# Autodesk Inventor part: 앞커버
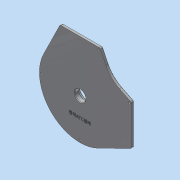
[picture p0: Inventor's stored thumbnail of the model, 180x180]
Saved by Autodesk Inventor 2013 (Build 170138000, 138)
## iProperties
Created: 2017-05
Part Number: 앞커버
Material: 알루미늄 6061
Document SubType Name: Modeling
Designer: mduedu
Density: 2.71 g/cm^3
Mass: 321.629 g
Surface Area: 500.043 cm^2
Volume: 118.682 cm^3
Author: mduedu
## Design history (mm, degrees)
sketch "스케치1"
  geometry: L1 (-71.801, 35.28)-(-40, 100); L2 (-40, 100)-(40, 100); L3 (40, 100)-(52.248, 75.073); L4 (35.28, 71.801)-(59.768, 59.768); L5 (100, 40)-(100, -40); L6 (100, -40)-(35.28, -71.801); L7 (75.073, 52.248)-(100, 40); L8 (59.768, 59.768)-(71.801, 35.28); L9 (33.075, -67.313)-(95, -36.886); L10 (95, -36.886)-(95, 36.886); L11 (95, 36.886)-(72.868, 47.76); L12 (47.76, 72.868)-(36.886, 95); L13 (36.886, 95)-(-36.886, 95); L14 (-36.886, 95)-(-67.313, 33.075); A1 r 80 centre (0, 0) between (71.801, 35.28) and (-71.801, 35.28); A2 r 80 centre (0, 0) between (35.28, -71.801) and (71.801, 35.28); A3 r 80 centre (0, 0) between (-71.801, 35.28) and (35.28, -71.801); A4 r 50 centre (97.123, 97.123) between (52.248, 75.073) and (75.073, 52.248); A5 r 55 centre (97.123, 97.123) between (47.76, 72.868) and (72.868, 47.76); A6 r 75 centre (0, 0) between (-67.313, 33.075) and (33.075, -67.313); 3 further points
  constraints: 29 end point, 15 tangent, 14 point on circle, 6 centre point, 2 midpoint, 2 perpendicular, 2 point on line, 1 coincident, 1 horizontal, 1 horizontal alignment, 1 vertical alignment, 6 other
  dimensions: "d0" = 160 diameter of A1; "d1" = 100 distance from line of L2 point (0, 0); "d2" = 100 distance from line of L5 point (0, 0); "d3" = 80 distance of L1.end L2.end; "d4" = 80 distance of L5.start L5.end; "d5" = 50 radius of A4; "d6" = 5 distance between parallel lines of L13 L2
extrude "돌출1" new body sketch "스케치1" distance "d7" = 5; taper "d8" = 0 deg
fillet "모깎기1" dims "d9" = 3
sketch "스케치2"
  geometry: C1 r 22 at (0, 0); 1 further point
  constraints: 1 centre point, 1 coincident
  dimensions: "d10" = 44 diameter of C1
extrude "돌출2" join sketch "스케치2" distance "d11" = 12.5; taper "d12" = 0 deg
sketch "스케치3"
  geometry: C1 r 18.5 at (0, 0); 1 further point
  constraints: 1 centre point, 1 coincident
  dimensions: "d13" = 37 diameter of C1
extrude "돌출3" cut sketch "스케치3" distance "d14" = 9; taper "d15" = 0 deg
hole "구멍1" diameter "d18" = 20; stored, may be unused: countersink angle "d22" = 90 deg, drill point angle "d24" = 118 deg; dims "d16" = 10, "d17" = 10, "d19" = 6, "d20" = 4, "d21" = 2, "d23" = 8
fillet "모깎기2" dims "d25" = 3
chamfer "모따기1" distance "d27" = 1; stored, may be unused: second distance "d28" = 2, angle "d29" = 45 deg
sketch "스케치4"
  geometry: 2 further points
  constraints: 1 vertical alignment, 1 other
  dimensions: "d30" = 35 distance of point (0, -35) point (0, 0)
feature "엠보싱1" sketch "스케치4" dims "d31" = 0.5, "d32" = 0
chamfer "모따기2" distance "d33" = 1; stored, may be unused: second distance "d34" = 2, angle "d35" = 45 deg
chamfer "모따기3" distance "d36" = 1; stored, may be unused: second distance "d37" = 2, angle "d38" = 45 deg
sketch "스케치5"
  geometry: L1 (18.989, -35.003)-(17.659, -35.003) reference; L2 (17.659, -35.003)-(17.659, -34.623) reference; L3 (17.659, -34.623)-(18.989, -34.623) reference; L4 (18.989, -34.623)-(18.989, -32.045) reference; L5 (18.989, -32.045)-(19.315, -32.045) reference; L6 (19.45, -32.31)-(19.45, -37.982) reference; L7 (19.45, -37.982)-(18.989, -37.982) reference; L8 (18.989, -37.982)-(18.989, -35.003) reference; L9 (-13.942, -34.352)-(-13.942, -34.746) reference; L10 (-13.942, -34.746)-(-15.061, -34.746) reference; L11 (-15.061, -34.746)-(-15.061, -36.489) reference; L12 (-15.061, -36.489)-(-15.536, -36.489) reference; L13 (-15.536, -36.489)-(-15.536, -31.998) reference; L14 (-15.536, -31.998)-(-15.231, -31.998) reference; L15 (-15.061, -32.263)-(-15.061, -34.352) reference; L16 (-15.061, -34.352)-(-13.942, -34.352) reference; L17 (-14.844, -37.439)-(-14.844, -37.819) reference; L18 (-14.844, -37.819)-(-19.193, -37.819) reference; L19 (-19.193, -37.819)-(-19.193, -36.191) reference; L20 (-19.193, -36.191)-(-18.84, -36.191) reference; L21 (-18.731, -36.408)-(-18.731, -37.439) reference; L22 (-18.731, -37.439)-(-14.844, -37.439) reference; L23 (-17.374, -32.575)-(-18.853, -32.575) reference; L24 (-18.853, -32.575)-(-18.853, -32.222) reference; L25 (-18.853, -32.222)-(-17.374, -32.222) reference; L26 (-17.374, -32.222)-(-17.374, -32.575) reference; L27 (-20.047, -33.382)-(-20.047, -33.029) reference; L28 (-20.047, -33.029)-(-16.282, -33.029) reference; L29 (-16.282, -33.029)-(-16.282, -33.382) reference; L30 (-16.282, -33.382)-(-20.047, -33.382) reference; L31 (-2.917, -37.615)-(-3.474, -36.089) reference; L32 (-3.474, -36.089)-(-5.726, -36.089) reference; L33 (-5.726, -36.089)-(-6.296, -37.615) reference; L34 (-6.296, -37.615)-(-6.777, -37.615) reference; L35 (-6.777, -37.615)-(-4.878, -32.615) reference; L36 (-4.878, -32.615)-(-4.335, -32.615) reference; L37 (-4.335, -32.615)-(-2.436, -37.615) reference; L38 (-2.436, -37.615)-(-2.917, -37.615) reference; L39 (-4.613, -33.104)-(-5.57, -35.675) reference; L40 (-5.57, -35.675)-(-3.636, -35.675) reference; L41 (-3.636, -35.675)-(-4.613, -33.104) reference; L42 (-10.095, -35.851)-(-8.284, -35.851) reference; L43 (-8.284, -35.851)-(-8.284, -37.975) reference; L44 (-8.284, -37.975)-(-8.745, -37.975) reference; L45 (-8.745, -37.975)-(-8.745, -36.225) reference; L46 (-8.745, -36.225)-(-12.578, -36.225) reference; L47 (-12.578, -36.225)-(-12.578, -35.851) reference; L48 (-12.578, -35.851)-(-10.55, -35.851) reference; L49 (-10.55, -35.851)-(-10.55, -34.63) reference; L50 (-10.55, -34.63)-(-13.311, -34.63) reference; L51 (-13.311, -34.63)-(-13.311, -34.257) reference; L52 (-13.311, -34.257)-(-8.942, -34.257) reference; L53 (-8.657, -32.588)-(-12.463, -32.588) reference; L54 (-12.463, -32.588)-(-12.463, -32.208) reference; L55 (-12.463, -32.208)-(-8.175, -32.208) reference; L56 (-8.446, -34.257)-(-7.307, -34.257) reference; L57 (-7.307, -34.257)-(-7.307, -34.63) reference; L58 (-7.307, -34.63)-(-10.095, -34.63) reference; L59 (-10.095, -34.63)-(-10.095, -35.851) reference; L60 (1.526, -32.615)-(1.526, -33.029) reference; L61 (1.526, -33.029)-(-0.034, -33.029) reference; L62 (-0.034, -33.029)-(-0.034, -37.615) reference; L63 (-0.034, -37.615)-(-0.488, -37.615) reference; L64 (-0.488, -37.615)-(-0.488, -33.029) reference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; C1 r 11 at (0, 0) reference; C2 r 4 at (-71, 0); C3 r 4 at (0, -71); C4 r 4 at (91, 34.394); C5 r 4 at (34.394, 91); A1 r 75 centre (0, 0) between (-67.313, 33.075) and (33.075, -67.313) reference; A2 r 3 centre (-35.017, 92) between (-35.017, 95) and (-37.71, 93.323) reference; A3 r 3 centre (35.017, 92) between (37.71, 93.323) and (35.017, 95) reference; A4 r 55 centre (97.123, 97.123) between (47.76, 72.868) and (72.868, 47.76) reference; A5 r 3 centre (92, 35.017) between (95, 35.017) and (93.323, 37.71) reference; A6 r 3 centre (92, -35.017) between (93.323, -37.71) and (95, -35.017) reference; A7 r 75 centre (0, 0) between (-67.313, 33.075) and (33.075, -67.313) reference; 66 further points
  constraints: 6 tangent, 4 centre point, 4 coincident, 3 equal radius, 1 horizontal alignment, 1 vertical alignment, 76 other
  dimensions: "d39" = 8 diameter of C2
  node "절단 모서리 투영1"
sketch "스케치6"
  geometry: 4 further points
  constraints: 4 other
hole "구멍2" sketch "스케치6" at (0, -71), (91, 34.394), (34.394, 91), (-71, 0) diameter "d40" = 3.4; stored, may be unused: countersink angle "d44" = 90 deg, drill point angle "d46" = 0 deg; dims "d41" = 6, "d42" = 4, "d43" = 2, "d45" = 8
node "솔리드1"
